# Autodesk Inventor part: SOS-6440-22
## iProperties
Author: Ron Crain
Shininess: 25.0
Angle Display Precision: 2
Document Length Units: 11272
Document Angle Units: 11286
Document Time Units: 11279
Document Mass Units: 11290
Document Length Units Precision: 3
Document Angle Units Precision: 2
Compacted: True
PropertySet Name: _Private Model Information
Created: 2001-09
Part Number: SOS-6440-22
Material: Stainless Steel, Austenitic
Description: STANDOFF, THRU HOLE THREADED , SELF CLINCH, 4-40 UNC X 0.6875
Vendor: PENN ENG. & MFG
Document SubType Name: Modeling
Designer: Ron Crain
Control State: 0
Master: False
Checked Out: False
PropertySet Name: Design Tracking Control
Density: 7.84
Volumn: 0.17245559573138858
Area: 3.4800931280430336
PropertySet Name: Model Information
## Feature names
1. Extrusion1
2. Extrusion2
3. Revolution1
4. Revolution2
5. Rectangular Pattern1
6. Hole1
7. Chamfer5
8. Hole4
9. Chamfer3
